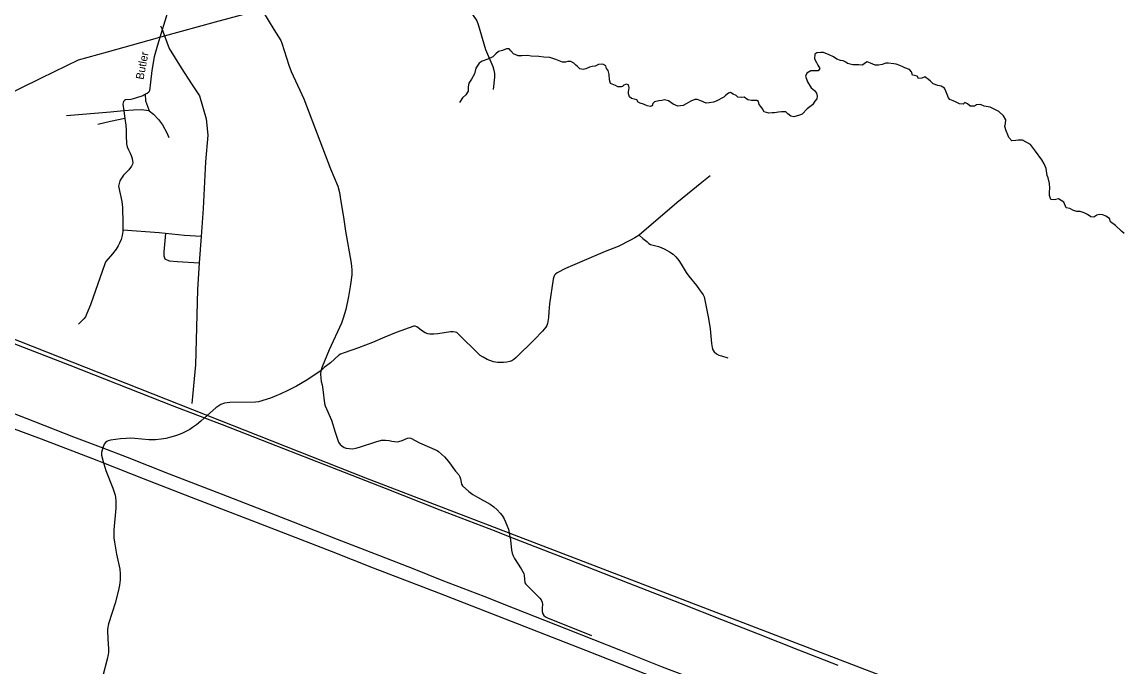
# Model space of a CAD drawing. Extents: x 2225501 to 2309677, y 165449 to 227696.
# Drawn here: x 2267922 to 2280990, y 197321 to 204979 of the extents above; entities that cross this region are included whole.
import ezdxf

# ---------------------------------------------------------------- set-up
doc = ezdxf.new("R2010")
doc.units = 0
for name, color, linetype in [('Black Area Fill Shapes', 7, 'Continuous'), ('MARK ENDS WORD SYMBOL CELL', 7, 'Continuous'), ('Old_Level_3', 7, 'Continuous'), ('Old_Level_33', 7, 'Continuous'), ('Old_Level_41', 7, 'Continuous'), ('Prop Support', 7, 'Continuous'), ('Typical Terminator CELL', 7, 'Continuous')]:
    doc.layers.add(name, color=color, linetype=linetype)

msp = doc.modelspace()

# ---------------------------------------------------------------- linework, layer by layer
at = {"layer": 'Black Area Fill Shapes'}
msp.add_line((2269528, 204791), (2269550, 204798), dxfattribs=at)
for points in [[(2269612, 204815), (2270217, 204979), (2270764, 205129)], [(2264390, 202506), (2265041, 202813), (2265649, 203104), (2266188, 203364), (2266912, 203713), (2267652, 204070), (2268155, 204315), (2268592, 204528), (2268935, 204625), (2269528, 204791)], [(2269550, 204798), (2269601, 204812), (2269612, 204815)], [(2264390, 202506), (2264826, 202337), (2265541, 202059), (2266209, 201803), (2266988, 201494), (2267824, 201162), (2268489, 200903), (2269182, 200632), (2269704, 200427), (2270089, 200279)], [(2265343, 201114), (2265814, 200932), (2266600, 200627), (2267366, 200318), (2268149, 200030), (2268810, 199775), (2268889, 199744)], [(2270089, 200279), (2270299, 200199), (2270865, 199977), (2271512, 199727), (2272233, 199443), (2272880, 199189), (2273547, 198932), (2273714, 198868)], [(2268889, 199744), (2269360, 199561), (2269931, 199338), (2270754, 199020), (2271590, 198697), (2272090, 198499), (2272866, 198202), (2273728, 197866), (2274609, 197521), (2275433, 197198), (2276180, 196909), (2276769, 196681), (2277420, 196425), (2278147, 196143)], [(2273714, 198868), (2274409, 198598), (2275126, 198315), (2275745, 198076), (2276225, 197887), (2276659, 197714), (2277139, 197524), (2277607, 197342)]]:
    msp.add_lwpolyline(points, dxfattribs=at)
at = {"layer": 'Old_Level_3'}
for p, q in [((2269567, 204935), (2269580, 204902)), ((2269580, 204902), (2269612, 204815)), ((2269131, 203923), (2269143, 203835)), ((2270049, 202433), (2270026, 202120))]:
    msp.add_line(p, q, dxfattribs=at)
for points in [[(2272857, 205714), (2272903, 205595), (2272936, 205526), (2273060, 205369), (2273142, 205252), (2273209, 205149), (2273268, 205068), (2273319, 204992), (2273335, 204949), (2273423, 204654), (2273509, 204449), (2273522, 204405), (2273529, 204367), (2273529, 204325), (2273513, 204177)], [(2270775, 205111), (2270911, 204888), (2270994, 204758), (2271006, 204728), (2271087, 204465), (2271115, 204390), (2271245, 204119), (2271268, 204065), (2271584, 203237), (2271671, 203028), (2271692, 202954), (2271699, 202899), (2271742, 202635), (2271762, 202497), (2271830, 202114), (2271838, 202036), (2271836, 201979), (2271821, 201862), (2271797, 201718), (2271765, 201564), (2271735, 201461), (2271713, 201403), (2271569, 201085), (2271486, 200886), (2271468, 200838)], [(2269612, 204815), (2269669, 204664), (2269809, 204436), (2269932, 204243), (2270029, 204102), (2270064, 203979), (2270108, 203830), (2270126, 203636), (2270099, 203320), (2270073, 202766), (2270049, 202433)], [(2269434, 204162), (2269426, 204146), (2269409, 204130), (2269385, 204121)], [(2269381, 204118), (2269356, 204102), (2269268, 204073), (2269212, 204060), (2269149, 204053), (2269139, 204045), (2269125, 204033), (2269119, 204003), (2269131, 203923)], [(2269385, 204121), (2269389, 204042), (2269411, 203980), (2269433, 203923)], [(2269131, 203923), (2268972, 203910), (2268449, 203866)], [(2269433, 203923), (2269336, 203936), (2269244, 203932), (2269131, 203923)], [(2269433, 203923), (2269481, 203883), (2269543, 203822), (2269591, 203756), (2269639, 203664), (2269666, 203607)], [(2269143, 203835), (2268971, 203799), (2268822, 203763)], [(2269143, 203835), (2269156, 203753), (2269159, 203695), (2269158, 203633), (2269163, 203533), (2269171, 203498), (2269184, 203462), (2269206, 203422), (2269219, 203392), (2269229, 203360), (2269235, 203330), (2269236, 203308), (2269232, 203290), (2269220, 203266), (2269191, 203224), (2269128, 203159), (2269102, 203125), (2269083, 203092), (2269073, 203062), (2269069, 203028), (2269105, 202849), (2269114, 202777), (2269118, 202589), (2269117, 202508)], [(2276092, 203153), (2275991, 203075), (2275695, 202830), (2275246, 202448)], [(2269117, 202508), (2269117, 202492), (2269110, 202445), (2269097, 202396), (2269079, 202352), (2269064, 202322), (2269038, 202282), (2268995, 202226), (2268918, 202136), (2268904, 202108), (2268733, 201620), (2268692, 201517), (2268674, 201480), (2268656, 201455), (2268593, 201393)], [(2269625, 202466), (2269548, 202474), (2269117, 202508)], [(2269625, 202466), (2269614, 202338), (2269605, 202250), (2269605, 202202), (2269618, 202167), (2269667, 202145), (2269768, 202136), (2270026, 202120)], [(2270049, 202433), (2269851, 202444), (2269625, 202466)], [(2275246, 202448), (2275197, 202416), (2275146, 202387), (2274998, 202314), (2274845, 202255), (2274373, 202054), (2274274, 202000), (2274254, 201984), (2274244, 201972), (2274234, 201954), (2274225, 201924), (2274184, 201633), (2274175, 201537), (2274172, 201469), (2274159, 201399), (2274151, 201375), (2274140, 201357), (2274100, 201310), (2274002, 201205), (2273786, 200995), (2273761, 200972), (2273737, 200958), (2273711, 200948), (2273677, 200939), (2273637, 200935), (2273566, 200935), (2273517, 200943), (2273445, 200970), (2273394, 200998), (2273362, 201021), (2273083, 201292), (2273065, 201298), (2273038, 201301), (2273008, 201301), (2272859, 201275), (2272812, 201272), (2272763, 201274), (2272737, 201277), (2272709, 201287), (2272674, 201307), (2272610, 201358), (2272587, 201368), (2272574, 201369), (2272363, 201293), (2272227, 201237), (2272082, 201173), (2271917, 201109), (2271747, 201052), (2271703, 201034), (2271684, 201022), (2271583, 200931), (2271510, 200875), (2271468, 200838)], [(2275246, 202448), (2275291, 202407), (2275337, 202372), (2275361, 202350), (2275383, 202338), (2275476, 202313), (2275510, 202300), (2275554, 202280), (2275607, 202251), (2275649, 202221), (2275681, 202190), (2275717, 202149), (2275747, 202104), (2275806, 202005), (2275836, 201962), (2275928, 201849), (2275962, 201799), (2275987, 201769), (2276007, 201740), (2276017, 201714), (2276032, 201658), (2276072, 201457), (2276090, 201335), (2276106, 201163), (2276113, 201116), (2276123, 201085), (2276139, 201064), (2276164, 201041), (2276195, 201025), (2276223, 201014), (2276298, 200991)], [(2270026, 202120), (2270003, 201800), (2269981, 200908), (2269937, 200451)], [(2271468, 200838), (2271296, 200722), (2271179, 200656), (2271077, 200603), (2270995, 200564), (2270920, 200531), (2270870, 200512), (2270727, 200469), (2270695, 200464), (2270389, 200461), (2270327, 200454), (2270282, 200439), (2270223, 200399), (2270089, 200279)], [(2271468, 200838), (2271465, 200796), (2271467, 200752), (2271474, 200712), (2271484, 200670), (2271493, 200616), (2271511, 200450), (2271519, 200423), (2271597, 200252), (2271637, 200110), (2271677, 199992), (2271697, 199963), (2271719, 199945), (2271745, 199929), (2271768, 199921), (2271806, 199914), (2271848, 199913), (2271884, 199919), (2271929, 199932), (2272121, 199994), (2272190, 200013), (2272238, 200016), (2272278, 200012), (2272311, 200002), (2272373, 199993), (2272396, 199997), (2272436, 200012), (2272496, 200038), (2272518, 200041), (2272536, 200037), (2272641, 199982), (2272850, 199891), (2272866, 199879), (2272935, 199816), (2272985, 199762), (2273069, 199646), (2273105, 199602), (2273118, 199580), (2273128, 199554), (2273139, 199491), (2273149, 199473), (2273224, 199406), (2273274, 199370), (2273327, 199337), (2273478, 199255), (2273522, 199223), (2273563, 199186), (2273599, 199148), (2273621, 199120), (2273644, 199079), (2273677, 199007), (2273695, 198958), (2273710, 198890), (2273714, 198868)], [(2270089, 200279), (2270046, 200240), (2269992, 200196), (2269947, 200163), (2269913, 200141), (2269874, 200121), (2269818, 200094), (2269756, 200071), (2269690, 200049), (2269628, 200034), (2269574, 200025), (2269506, 200018), (2269428, 200017), (2269260, 200033), (2269204, 200037), (2269158, 200035), (2269092, 200030), (2268974, 200013), (2268944, 200005), (2268927, 199997), (2268911, 199985), (2268897, 199968), (2268881, 199922)], [(2268881, 199922), (2268872, 199896), (2268866, 199866), (2268867, 199838), (2268889, 199744)], [(2268889, 199744), (2268892, 199732), (2268917, 199656), (2268998, 199445), (2269028, 199361), (2269033, 199334), (2269037, 199294), (2269036, 199206), (2269013, 198950), (2269013, 198856), (2269019, 198805), (2269045, 198662), (2269081, 198483), (2269086, 198429), (2269087, 198357), (2269078, 198292), (2269067, 198232), (2269028, 198078), (2268992, 197969), (2268950, 197832), (2268938, 197770), (2268936, 197742), (2268944, 197590), (2268949, 197546), (2268948, 197492), (2268945, 197468), (2268934, 197416), (2268780, 196819)], [(2273714, 198868), (2273719, 198832), (2273733, 198708), (2273739, 198672), (2273751, 198640), (2273768, 198608), (2273847, 198486), (2273878, 198430), (2273884, 198408), (2273891, 198322), (2273901, 198304), (2274069, 198140), (2274086, 198120), (2274097, 198091), (2274101, 198062), (2274095, 198024), (2274095, 197981), (2274102, 197953), (2274116, 197931), (2274136, 197915), (2274160, 197904), (2274681, 197696)]]:
    msp.add_lwpolyline(points, dxfattribs=at)
at = {"layer": 'Old_Level_33'}
msp.add_lwpolyline([(2269967, 206192), (2269918, 206000), (2269823, 205673), (2269618, 204987), (2269528, 204705), (2269492, 204567), (2269464, 204402), (2269445, 204266), (2269434, 204162)], dxfattribs=at)
at = {"layer": 'Old_Level_41'}
msp.add_lwpolyline([(2267396, 200499), (2268070, 200237), (2268534, 200054), (2268881, 199922), (2269170, 199812), (2269667, 199615), (2270286, 199376), (2270713, 199209), (2271139, 199044), (2271663, 198840), (2272166, 198644), (2272574, 198485), (2272905, 198353), (2273403, 198161), (2273753, 198023), (2274386, 197776), (2275025, 197521), (2275521, 197325), (2276043, 197125), (2276429, 196975), (2276734, 196855), (2276961, 196766)], dxfattribs=at)
at = {"layer": 'Prop Support'}
msp.add_lwpolyline([(2284408, 194805), (2272002, 199563), (2267570, 201312)], dxfattribs=at)
at = {"layer": 'Typical Terminator CELL'}
msp.add_line((2273152, 204077), (2273114, 204025), dxfattribs=at)
for points in [[(2276672, 203998), (2276665, 204033), (2276646, 204046), (2276616, 204046), (2276580, 204046), (2276536, 204053), (2276492, 204085), (2276461, 204082), (2276418, 204087), (2276397, 204107), (2276364, 204123), (2276333, 204143), (2276306, 204133), (2276274, 204107), (2276252, 204085), (2276162, 204039), (2276129, 204026), (2276077, 204019), (2276043, 204017), (2275980, 204044), (2275936, 204060), (2275907, 204057), (2275861, 204037), (2275805, 204008), (2275769, 203989), (2275708, 203981), (2275651, 204004), (2275594, 204043), (2275548, 204053), (2275515, 204048), (2275480, 204041), (2275428, 204030), (2275410, 204010), (2275400, 203982), (2275379, 203974), (2275341, 203984), (2275297, 204003), (2275261, 204015), (2275236, 204028), (2275218, 204053), (2275187, 204064), (2275156, 204069), (2275133, 204092), (2275122, 204126), (2275120, 204151), (2275128, 204199), (2275122, 204233), (2275095, 204241), (2275058, 204223), (2275053, 204213), (2275036, 204208), (2274994, 204210), (2274966, 204223), (2274909, 204248), (2274894, 204292), (2274892, 204354), (2274879, 204401), (2274859, 204426), (2274850, 204460), (2274818, 204477), (2274766, 204475), (2274725, 204454), (2274691, 204449), (2274658, 204444), (2274615, 204424), (2274584, 204414), (2274545, 204422), (2274515, 204449), (2274496, 204468), (2274473, 204491), (2274438, 204508), (2274399, 204508), (2274373, 204501), (2274337, 204503), (2274260, 204535), (2274186, 204559), (2274117, 204563), (2274055, 204569), (2273966, 204573), (2273922, 204581), (2273855, 204579), (2273811, 204577), (2273756, 204602), (2273725, 204635), (2273704, 204662), (2273671, 204662), (2273624, 204642), (2273579, 204627), (2273545, 204600), (2273509, 204565), (2273453, 204537), (2273383, 204513), (2273350, 204490), (2273309, 204432), (2273291, 204363), (2273257, 204300), (2273227, 204253), (2273217, 204210), (2273216, 204156), (2273191, 204115), (2273152, 204077)], [(2279746, 203577), (2279720, 203572), (2279669, 203569), (2279635, 203607), (2279623, 203639), (2279602, 203687), (2279586, 203738), (2279596, 203772), (2279599, 203816), (2279571, 203866), (2279517, 203918), (2279412, 203967), (2279342, 203981), (2279301, 203998), (2279253, 203994), (2279227, 203978), (2279176, 203978), (2279145, 204009), (2279115, 204022), (2279094, 204004), (2279051, 204008), (2279001, 204030), (2278974, 204042), (2278937, 204057), (2278919, 204080), (2278886, 204156), (2278873, 204195), (2278832, 204217), (2278791, 204226), (2278737, 204244), (2278706, 204276), (2278681, 204297), (2278640, 204326), (2278601, 204313), (2278565, 204308), (2278548, 204335), (2278516, 204343), (2278493, 204349), (2278481, 204389), (2278457, 204415), (2278401, 204433), (2278378, 204445), (2278342, 204464), (2278299, 204479), (2278271, 204482), (2278204, 204490), (2278175, 204490), (2278130, 204475), (2278088, 204468), (2278047, 204467), (2277993, 204490), (2277955, 204504), (2277921, 204486), (2277898, 204467), (2277855, 204470), (2277829, 204470), (2277785, 204472), (2277722, 204485), (2277699, 204501), (2277670, 204519), (2277637, 204521), (2277595, 204536), (2277554, 204565), (2277503, 204590), (2277437, 204615), (2277404, 204615), (2277357, 204614), (2277334, 204595), (2277329, 204541), (2277352, 204499), (2277368, 204468), (2277390, 204427), (2277372, 204397), (2277327, 204397), (2277286, 204397), (2277239, 204372), (2277221, 204337), (2277245, 204267), (2277291, 204198), (2277327, 204167), (2277354, 204135), (2277362, 204099), (2277357, 204068), (2277332, 204037), (2277304, 203994), (2277241, 203948), (2277183, 203885), (2277149, 203873), (2277082, 203853), (2277049, 203862), (2277014, 203888), (2276987, 203912), (2276936, 203912), (2276900, 203907), (2276852, 203902), (2276828, 203900), (2276785, 203898), (2276731, 203913), (2276710, 203946), (2276690, 203976), (2276672, 203998)], [(2281003, 202466), (2280974, 202497), (2280902, 202563), (2280844, 202608), (2280831, 202645), (2280787, 202673), (2280753, 202691), (2280715, 202695), (2280680, 202685), (2280643, 202660), (2280607, 202664), (2280569, 202693), (2280530, 202713), (2280482, 202729), (2280441, 202729), (2280403, 202741), (2280358, 202765), (2280315, 202772), (2280287, 202840), (2280223, 202878), (2280177, 202868), (2280135, 202873), (2280117, 202920), (2280120, 202960), (2280123, 203007), (2280120, 203061), (2280104, 203127), (2280089, 203158), (2280079, 203240), (2280054, 203294), (2280027, 203342), (2279950, 203444), (2279891, 203526), (2279799, 203574), (2279746, 203577)]]:
    msp.add_lwpolyline(points, dxfattribs=at)

# ---------------------------------------------------------------- texts
at = {"layer": 'MARK ENDS WORD SYMBOL CELL'}
msp.add_text('Butler', height=95, rotation=79.3209, dxfattribs=at).set_placement((2269363, 204289))

doc.saveas('drawing.dxf')
